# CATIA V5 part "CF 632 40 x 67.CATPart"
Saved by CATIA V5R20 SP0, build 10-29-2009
Part number: CF 632 40 x 67
Definition: NONE
Nomenclature: CF 632 40 x 67
Source: Unknown
Description: CF 632 40 x 67
Bounding box of the stored display mesh (mm): x -13 to 54, y -31.5 to 31.5, z -31.5 to 31.5
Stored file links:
  C:\Users\Utente\Desktop\IO LAVORO\3D X SITO CF\X SITO\CF 632\CF 632 40 x 67.CATPart
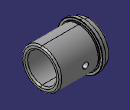
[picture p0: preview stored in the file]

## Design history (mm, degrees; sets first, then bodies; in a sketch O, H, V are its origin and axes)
Body1 "CF 632 40 x 67" (main body)
  Solid1: solid without history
